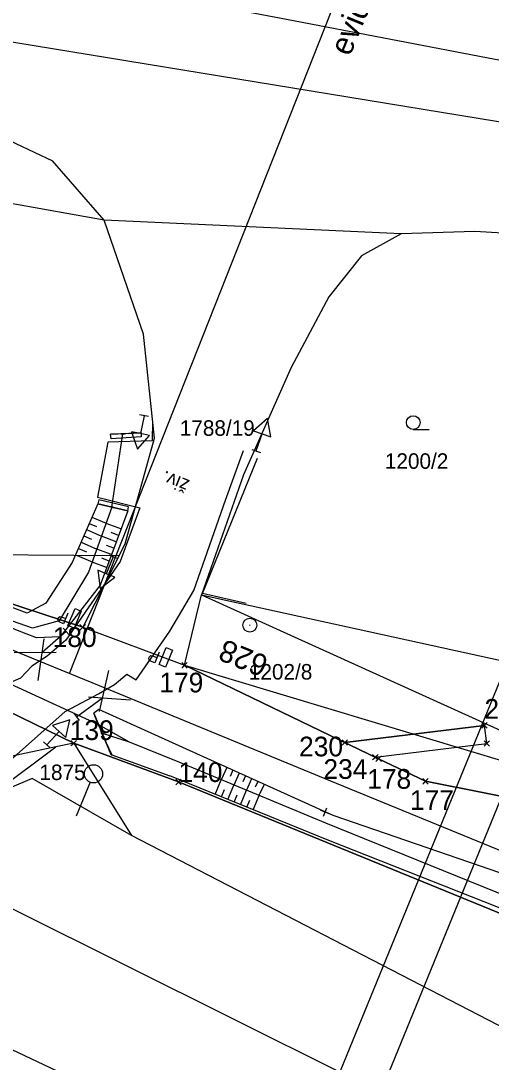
# Model space of a CAD drawing. Extents: x -779302 to -774398, y -1144902 to -1142831.
# Drawn here: x -776976.6 to -776925.1, y -1143911.3 to -1143797.2 of the extents above; entities that cross this region are included whole.
import ezdxf

# ---------------------------------------------------------------- set-up
doc = ezdxf.new("R2010")
doc.units = 0
for name, color, linetype in [('Dočasný zábor - do 1 roku - ZPF', 7, 'Continuous'), ('Hranice parcel', 7, 'Continuous'), ('legenda I_5_2 - Vrstva 53', 7, 'Continuous'), ('Parcelní čísla', 7, 'Continuous'), ('SŽDC', 7, 'Continuous'), ('VBř', 7, 'Continuous'), ('Vnitřní kresba', 7, 'Continuous'), ('Vrstva 1', 7, 'Continuous'), ('zjednodus_g_situ-seda - Vrstva 1', 7, 'Continuous'), ('zjednodus_g_situ-seda - Vrstva 17', 7, 'Continuous'), ('zjednodus_g_situ-seda - Vrstva 19', 7, 'Continuous'), ('zjednodus_g_situ-seda - Vrstva 33', 7, 'Continuous'), ('zjednodus_g_situ-seda - Vrstva 36', 7, 'Continuous'), ('zjednodus_g_situ-seda - Vrstva 4', 7, 'Continuous'), ('zjednodus_g_situ-seda - Vrstva 48', 7, 'Continuous'), ('zjednodus_g_situ-seda - Vrstva 49', 7, 'Continuous'), ('zjednodus_g_situ-seda - Vrstva 51', 7, 'Continuous'), ('zjednodus_g_situ-seda - Vrstva 63', 7, 'Continuous'), ('zjednodus_g_situ-seda - Vrstva 7', 7, 'Continuous'), ('Značky kultur', 7, 'Continuous')]:
    doc.layers.add(name, color=color, linetype=linetype)

msp = doc.modelspace()

# ---------------------------------------------------------------- linework, layer by layer
at = {"layer": 'Dočasný zábor - do 1 roku - ZPF'}
for p, q in [((-776941.1, -1143876.29), (-776925.79, -1143874.41)), ((-776925.79, -1143874.41), (-776941.1, -1143876.29)), ((-776925.54, -1143876.39), (-776925.79, -1143874.41)), ((-776941.1, -1143876.29), (-776937.76, -1143877.9)), ((-776937.76, -1143877.9), (-776925.54, -1143876.39)), ((-776937.76, -1143877.9), (-776937.76, -1143877.9))]:
    msp.add_line(p, q, dxfattribs=at)
msp.add_lwpolyline([(-776937.76, -1143877.9), (-776925.54, -1143876.39), (-776925.79, -1143874.41)], dxfattribs=at)
at = {"layer": 'Hranice parcel'}
for p, q in [((-776934.92, -1143820.52), (-776967.5, -1143819.04)), ((-776965.83, -1143855.79), (-776969.85, -1143863.66)), ((-776958.69, -1143867.83), (-776956.82, -1143860.1)), ((-776956.82, -1143860.1), (-776921.24, -1143867.89)), ((-776969.85, -1143863.66), (-776958.69, -1143867.83)), ((-776970.83, -1143876.37), (-776972.79, -1143876.78)), ((-776970.83, -1143876.37), (-776964.5, -1143886.48)), ((-776980.14, -1143882.23), (-776972.79, -1143876.78))]:
    msp.add_line(p, q, dxfattribs=at)
for points in [[(-776969.85, -1143863.66), (-776987.47, -1143857.88), (-777014.89, -1143846.57), (-777042.6, -1143836.95), (-777069.03, -1143828.43), (-777082.24, -1143824.08), (-777130.76, -1143810.13), (-777274.26, -1143769.36), (-777322.71, -1143754.8), (-777354.97, -1143745.11)], [(-777032.87, -1143780.76), (-777005.26, -1143786.02), (-776947.51, -1143797.01), (-776924.63, -1143801.37), (-776885.75, -1143807.75)], [(-776967.5, -1143819.04), (-777009.69, -1143811.52), (-777037.53, -1143806.56)], [(-776965.83, -1143855.79), (-776965.18, -1143854.52), (-776961.99, -1143842.94), (-776963.17, -1143831.52), (-776967.5, -1143819.04)], [(-776934.92, -1143820.52), (-776939.26, -1143822.95), (-776942.87, -1143827.42), (-776947, -1143835.19), (-776952.22, -1143846.94), (-776956.82, -1143860.1)], [(-776913.94, -1143821.03), (-776926.85, -1143820.27), (-776934.92, -1143820.52)], [(-777042.47, -1143834.85), (-777015.21, -1143843.76), (-776985.79, -1143855.66), (-776965.83, -1143855.79)], [(-776956.82, -1143860.1), (-776911.51, -1143880.63), (-776902.75, -1143884.6)], [(-777002.25, -1143861.05), (-776982.48, -1143870.69), (-776970.83, -1143876.37)], [(-776911.85, -1143884.6), (-776932.26, -1143880.54), (-776937.4, -1143878.07), (-776958.69, -1143867.83)], [(-776970.83, -1143876.37), (-776959.34, -1143880.62), (-776893.47, -1143907.54), (-776747.29, -1143966.09)], [(-776972.79, -1143876.78), (-776992.99, -1143881.07), (-776998.39, -1143882.22)], [(-776964.5, -1143886.48), (-776975.37, -1143880.22), (-776980.14, -1143882.23)], [(-776767.95, -1143981.96), (-776771.13, -1143981.54), (-776923.23, -1143907.82), (-776964.5, -1143886.48)], [(-776817.86, -1143983.94), (-776814.26, -1143974.07), (-776869.06, -1143948.13), (-776905.56, -1143930.42), (-776989.05, -1143888.84)], [(-776819.3, -1143987.88), (-776871.91, -1143959.94), (-776915.87, -1143938.7), (-776942.03, -1143926.84), (-776978.29, -1143909.65), (-777001.23, -1143897.87)]]:
    msp.add_lwpolyline(points, dxfattribs=at)
at = {"layer": 'legenda I_5_2 - Vrstva 53'}
for points in [[(-777442.54, -1143720.48), (-777400.53, -1143733.41), (-777370.73, -1143741.3), (-777366.62, -1143741.88), (-777364.22, -1143742.54), (-777360.64, -1143743.54), (-777354.97, -1143745.11), (-777322.71, -1143754.8), (-777274.26, -1143769.36), (-777130.76, -1143810.13), (-777082.24, -1143824.08), (-777069.03, -1143828.43), (-777042.6, -1143836.95), (-777014.89, -1143846.57), (-776987.47, -1143857.88), (-776969.85, -1143863.66), (-776958.69, -1143867.83), (-776937.4, -1143878.07), (-776932.26, -1143880.54), (-776911.85, -1143884.6)], [(-776893.47, -1143907.54), (-776959.34, -1143880.62), (-776970.83, -1143876.37), (-776982.48, -1143870.69)]]:
    msp.add_lwpolyline(points, dxfattribs=at)
at = {"layer": 'SŽDC'}
for p, q in [((-776969.65, -1143863.86), (-776970.15, -1143863.36)), ((-776969.65, -1143863.46), (-776970.15, -1143863.96)), ((-776970.05, -1143863.86), (-776969.55, -1143863.36)), ((-776970.05, -1143863.46), (-776969.55, -1143863.96)), ((-776969.85, -1143863.66), (-776969.85, -1143863.66)), ((-776958.49, -1143868.03), (-776958.99, -1143867.53)), ((-776958.89, -1143868.03), (-776958.39, -1143867.53)), ((-776958.49, -1143867.63), (-776958.99, -1143868.13)), ((-776958.89, -1143867.63), (-776958.39, -1143868.13)), ((-776958.69, -1143867.83), (-776958.69, -1143867.83)), ((-776970.63, -1143876.57), (-776971.13, -1143876.07)), ((-776970.63, -1143876.17), (-776971.13, -1143876.67)), ((-776971.03, -1143876.57), (-776970.53, -1143876.07)), ((-776971.03, -1143876.17), (-776970.53, -1143876.67)), ((-776970.83, -1143876.37), (-776970.83, -1143876.37)), ((-776937.2, -1143878.27), (-776937.7, -1143877.77)), ((-776937.2, -1143877.87), (-776937.7, -1143878.37)), ((-776937.6, -1143878.27), (-776937.1, -1143877.77)), ((-776937.6, -1143877.87), (-776937.1, -1143878.37)), ((-776937.4, -1143878.07), (-776937.4, -1143878.07)), ((-776959.14, -1143880.82), (-776959.64, -1143880.32)), ((-776959.14, -1143880.42), (-776959.64, -1143880.92)), ((-776959.54, -1143880.82), (-776959.04, -1143880.32)), ((-776959.54, -1143880.42), (-776959.04, -1143880.92)), ((-776959.34, -1143880.62), (-776959.34, -1143880.62)), ((-776932.06, -1143880.74), (-776932.56, -1143880.24)), ((-776932.06, -1143880.34), (-776932.56, -1143880.84)), ((-776932.46, -1143880.74), (-776931.96, -1143880.24)), ((-776932.46, -1143880.34), (-776931.96, -1143880.84)), ((-776932.26, -1143880.54), (-776932.26, -1143880.54))]:
    msp.add_line(p, q, dxfattribs=at)
for points in [[(-777442.54, -1143720.48), (-777400.53, -1143733.41), (-777370.73, -1143741.3), (-777366.62, -1143741.88), (-777364.22, -1143742.54), (-777360.64, -1143743.54), (-777354.97, -1143745.11), (-777322.71, -1143754.8), (-777274.26, -1143769.36), (-777130.76, -1143810.13), (-777082.24, -1143824.08), (-777069.03, -1143828.43), (-777042.6, -1143836.95), (-777014.89, -1143846.57), (-776987.47, -1143857.88), (-776969.85, -1143863.66), (-776958.69, -1143867.83), (-776937.4, -1143878.07), (-776932.26, -1143880.54), (-776911.85, -1143884.6)], [(-776098.59, -1144230.98), (-776104.51, -1144228.21), (-776116.08, -1144223.44), (-776126.28, -1144219.86), (-776203.96, -1144186.83), (-776252.27, -1144167.08), (-776325.22, -1144137.73), (-776342.13, -1144130.92), (-776434.38, -1144092.81), (-776527.2, -1144055.02), (-776604.66, -1144024.21), (-776606.85, -1144023.34), (-776609.89, -1144021.72), (-776627.91, -1144012.39), (-776712.36, -1143980.08), (-776747.29, -1143966.09), (-776893.47, -1143907.54), (-776959.34, -1143880.62), (-776970.83, -1143876.37), (-776982.48, -1143870.69)]]:
    msp.add_lwpolyline(points, dxfattribs=at)
at = {"layer": 'VBř'}
for p, q in [((-776941.1, -1143876.29), (-776925.79, -1143874.41)), ((-776925.79, -1143874.41), (-776941.1, -1143876.29)), ((-776925.59, -1143874.61), (-776926.09, -1143874.11)), ((-776925.59, -1143874.21), (-776926.09, -1143874.71)), ((-776925.99, -1143874.61), (-776925.49, -1143874.11)), ((-776925.99, -1143874.21), (-776925.49, -1143874.71)), ((-776925.54, -1143876.39), (-776925.79, -1143874.41)), ((-776925.79, -1143874.41), (-776925.79, -1143874.41)), ((-776940.9, -1143876.49), (-776941.4, -1143875.99)), ((-776940.9, -1143876.09), (-776941.4, -1143876.59)), ((-776941.3, -1143876.49), (-776940.8, -1143875.99)), ((-776941.3, -1143876.09), (-776940.8, -1143876.59)), ((-776941.1, -1143876.29), (-776937.76, -1143877.9)), ((-776941.1, -1143876.29), (-776941.1, -1143876.29)), ((-776937.76, -1143877.9), (-776925.54, -1143876.39)), ((-776925.34, -1143876.59), (-776925.84, -1143876.09)), ((-776925.34, -1143876.19), (-776925.84, -1143876.69)), ((-776925.74, -1143876.59), (-776925.24, -1143876.09)), ((-776925.74, -1143876.19), (-776925.24, -1143876.69)), ((-776925.54, -1143876.39), (-776925.54, -1143876.39)), ((-776937.56, -1143878.1), (-776938.06, -1143877.6)), ((-776937.56, -1143877.7), (-776938.06, -1143878.2)), ((-776937.96, -1143878.1), (-776937.46, -1143877.6)), ((-776937.96, -1143877.7), (-776937.46, -1143878.2))]:
    msp.add_line(p, q, dxfattribs=at)
msp.add_lwpolyline([(-776937.76, -1143877.9), (-776925.54, -1143876.39), (-776925.79, -1143874.41)], dxfattribs=at)
at = {"layer": 'Vnitřní kresba'}
for p, q in [((-776909.93, -1143810.58), (-776980.28, -1143799.08)), ((-776981.09, -1143808.78), (-776973.15, -1143812.54)), ((-776967.5, -1143819.04), (-776973.15, -1143812.54)), ((-776958.69, -1143867.83), (-776918.2, -1143879.97))]:
    msp.add_line(p, q, dxfattribs=at)
at = {"layer": 'Vrstva 1'}
for points in [[(-775713.68, -1144238.31), (-776879.99, -1143761.57), (-776992.36, -1144036.48), (-775826.05, -1144513.22)], [(-775828.78, -1144506.7), (-776985.84, -1144033.74), (-776877.25, -1143768.09), (-775720.2, -1144241.05)]]:
    msp.add_lwpolyline(points, close=True, dxfattribs=at)
at = {"layer": 'zjednodus_g_situ-seda - Vrstva 1'}
for points in [[(-776976.22, -1143866.7), (-776986.48, -1143862.49), (-776998.36, -1143857.65), (-777010.89, -1143852.7), (-777023.89, -1143847.77), (-777036.16, -1143843.3), (-777048.78, -1143838.91), (-777061.58, -1143834.66), (-777074.36, -1143830.6), (-777086.89, -1143826.8), (-777099.41, -1143823.17), (-777109.99, -1143820.13), (-777122.39, -1143816.56)], [(-776922.15, -1143888.92), (-776942.01, -1143880.78), (-776966.41, -1143870.74), (-776976.22, -1143866.7)]]:
    msp.add_lwpolyline(points, dxfattribs=at)
at = {"layer": 'zjednodus_g_situ-seda - Vrstva 17'}
msp.add_lwpolyline([(-776951.91, -1143861.07), (-776956.7, -1143859.96), (-776950.68, -1143845.13)], dxfattribs=at)
at = {"layer": 'zjednodus_g_situ-seda - Vrstva 19'}
for p, q in [((-776966.65, -1143850.49), (-776965.44, -1143842.46)), ((-776968.15, -1143874.33), (-776979.28, -1143869.22))]:
    msp.add_line(p, q, dxfattribs=at)
for points in [[(-776963.44, -1143842.35), (-776963.45, -1143842.79), (-776966.74, -1143843.01), (-776966.78, -1143842.48), (-776963.44, -1143842.35)], [(-776963.44, -1143842.35), (-776965.44, -1143842.46), (-776966.78, -1143842.48)], [(-776964.91, -1143850.88), (-776964.81, -1143850.44), (-776968.08, -1143849.68), (-776968.2, -1143850.12), (-776964.91, -1143850.88)], [(-776964.91, -1143850.88), (-776966.65, -1143850.49), (-776968.2, -1143850.12)], [(-776968.15, -1143874.33), (-776967.94, -1143874.75), (-776967.94, -1143874.76), (-776967.79, -1143875.29), (-776967.79, -1143875.28), (-776966.65, -1143877.66), (-776966.73, -1143877.64), (-776968.62, -1143873.09), (-776968.15, -1143874.33)]]:
    msp.add_lwpolyline(points, dxfattribs=at)
for centre, major_axis, ratio, start_param, end_param in [((-776965.47, -1143842.45), (-0.205, 0.006), 0.009306, 4.429767, 8.016952), ((-776965.47, -1143842.45), (-0.205, 0.006), 0.009306, 6.269557, 10.712953), ((-776966.62, -1143850.49), (-0.194, 0.054), 0.018197, 4.831006, 9.404932), ((-776966.62, -1143850.49), (-0.194, 0.054), 0.018197, 1.451935, 4.831006), ((-776968.19, -1143874.26), (0.135, -0.275), 0.012816, 1.330754, 4.921196), ((-776968.19, -1143874.26), (0.135, -0.275), 0.012816, 4.921196, 9.434774)]:
    msp.add_ellipse(centre, major_axis=major_axis, ratio=ratio, start_param=start_param, end_param=end_param, dxfattribs=at)
at = {"layer": 'zjednodus_g_situ-seda - Vrstva 33'}
for points in [[(-776970.77, -1143863.75), (-776971.46, -1143863.47), (-776970.69, -1143861.6), (-776970, -1143861.89)], [(-776960.78, -1143868.04), (-776961.46, -1143867.75), (-776960.7, -1143865.89), (-776960.01, -1143866.17)]]:
    msp.add_lwpolyline(points, close=True, dxfattribs=at)
for points in [[(-776971.47, -1143862.11), (-776971.94, -1143863.27), (-776972.43, -1143863.07), (-776972.55, -1143862.97), (-776972.58, -1143862.74), (-776972.54, -1143862.63), (-776972.35, -1143862.48), (-776972.19, -1143862.5), (-776971.71, -1143862.7)], [(-776961.47, -1143866.4), (-776961.95, -1143867.56), (-776962.43, -1143867.36), (-776962.56, -1143867.25), (-776962.58, -1143867.02), (-776962.54, -1143866.92), (-776962.36, -1143866.77), (-776962.19, -1143866.79), (-776961.71, -1143866.99)]]:
    msp.add_lwpolyline(points, dxfattribs=at)
at = {"layer": 'zjednodus_g_situ-seda - Vrstva 36'}
for p, q in [((-776968.66, -1143879.73), (-776968.66, -1143879.73)), ((-776969.04, -1143880.65), (-776970.56, -1143884.35))]:
    msp.add_line(p, q, dxfattribs=at)
msp.add_circle((-776968.66, -1143879.73), 1, dxfattribs=at)
at = {"layer": 'zjednodus_g_situ-seda - Vrstva 4'}
for p, q in [((-776971.31, -1143868.72), (-776937.22, -1143782.62)), ((-776971.65, -1143864.12), (-776974.29, -1143866.44)), ((-776971.32, -1143864.5), (-776971.98, -1143863.75)), ((-776974.73, -1143869.48), (-776974.07, -1143864.92)), ((-776972.76, -1143866.43), (-776977.37, -1143866.47)), ((-776966.41, -1143870.74), (-776976.22, -1143866.7)), ((-776967, -1143868.39), (-776968.03, -1143872.88)), ((-776970.52, -1143873.48), (-776967.69, -1143871.38)), ((-776969.22, -1143871.27), (-776964.62, -1143871.6)), ((-776970.81, -1143873.08), (-776970.22, -1143873.88))]:
    msp.add_line(p, q, dxfattribs=at)
at = {"layer": 'zjednodus_g_situ-seda - Vrstva 48'}
for p, q in [((-776968.83, -1143851.58), (-776967.28, -1143852.25)), ((-776969.13, -1143852.27), (-776968.33, -1143852.61)), ((-776965.65, -1143852.88), (-776967.29, -1143852.28)), ((-776969.73, -1143853.64), (-776968.89, -1143854.01)), ((-776969.43, -1143852.95), (-776967.79, -1143853.66)), ((-776966.17, -1143854.29), (-776967.8, -1143853.69)), ((-776965.91, -1143853.59), (-776966.73, -1143853.28)), ((-776970.32, -1143855.02), (-776969.44, -1143855.4)), ((-776970.02, -1143854.33), (-776968.3, -1143855.08)), ((-776966.43, -1143854.99), (-776967.24, -1143854.69)), ((-776970.62, -1143855.71), (-776968.81, -1143856.49)), ((-776966.69, -1143855.7), (-776968.31, -1143855.1)), ((-776966.95, -1143856.4), (-776967.76, -1143856.1)), ((-776967.22, -1143857.1), (-776968.82, -1143856.51)), ((-776954.06, -1143879.02), (-776954.68, -1143880.38)), ((-776953.38, -1143879.33), (-776953.68, -1143880)), ((-776952.69, -1143879.64), (-776953.29, -1143880.95)), ((-776952.01, -1143879.95), (-776952.3, -1143880.59)), ((-776955.32, -1143881.98), (-776954.67, -1143880.38)), ((-776953.93, -1143882.54), (-776953.29, -1143880.95)), ((-776951.33, -1143880.26), (-776951.9, -1143881.53)), ((-776950.65, -1143880.57), (-776950.93, -1143881.19)), ((-776949.96, -1143880.88), (-776950.52, -1143882.1)), ((-776954.62, -1143882.26), (-776954.3, -1143881.46)), ((-776953.23, -1143882.82), (-776952.91, -1143882.03)), ((-776952.54, -1143883.11), (-776951.9, -1143881.53)), ((-776951.15, -1143883.67), (-776950.51, -1143882.1)), ((-776951.84, -1143883.39), (-776951.53, -1143882.6))]:
    msp.add_line(p, q, dxfattribs=at)
at = {"layer": 'zjednodus_g_situ-seda - Vrstva 49'}
msp.add_line((-776964.91, -1143850.88), (-776968.2, -1143850.12), dxfattribs=at)
for points in [[(-776968.2, -1143850.12), (-776971, -1143856.57), (-776973.89, -1143861.01), (-776975.92, -1143862.12), (-776984.87, -1143858.78), (-776998.01, -1143853.19), (-777022.63, -1143844.17), (-777047.12, -1143835.12), (-777072.37, -1143826.98), (-777098.75, -1143819.43)], [(-776966.65, -1143850.49), (-776969.22, -1143857.63), (-776972.42, -1143862.97), (-776975.34, -1143863.74), (-776985.5, -1143860.23), (-776998.08, -1143854.94), (-777010.13, -1143850.49), (-777022.9, -1143845.63), (-777035.32, -1143841.2), (-777047.81, -1143836.56), (-777060.73, -1143832.38), (-777073.56, -1143828.16), (-777086.22, -1143824.49), (-777098.73, -1143820.87)], [(-776964.91, -1143850.88), (-776967.94, -1143859.05), (-776972.31, -1143864.71), (-776974.92, -1143864.81), (-776977.17, -1143863.94), (-776985.5, -1143860.23)], [(-776632.28, -1144010.5), (-776655.24, -1144000.62), (-776678.59, -1143991.16), (-776699.81, -1143982.69), (-776720.93, -1143974.16), (-776739.27, -1143966.19), (-776740.46, -1143965.68), (-776743.6, -1143964.4), (-776744.85, -1143963.84), (-776767.74, -1143955.02), (-776787.78, -1143946.98), (-776802.96, -1143940.45), (-776815.44, -1143935.53), (-776839.01, -1143925.84), (-776864.39, -1143915.25), (-776887.92, -1143905.39), (-776903.55, -1143899.04), (-776922.93, -1143890.99), (-776942.4, -1143884.3), (-776968.09, -1143872.66), (-776968.62, -1143873.09), (-776966.73, -1143877.64), (-776966.65, -1143877.66), (-776960.31, -1143879.96)], [(-776964.72, -1143876.26), (-776968.15, -1143874.33), (-776968.62, -1143873.09)], [(-776745.22, -1143966.39), (-776768.57, -1143956.81), (-776788.05, -1143948.79), (-776815.75, -1143937.29), (-776840.44, -1143927.18), (-776864.63, -1143917.51), (-776887.35, -1143908.08), (-776904.88, -1143900.89), (-776924.52, -1143892.68), (-776943.18, -1143885.14), (-776959.2, -1143878.5), (-776964.72, -1143876.26), (-776967.79, -1143875.28), (-776966.65, -1143877.66)], [(-776744.57, -1143967.58), (-776769.47, -1143958.42), (-776788.11, -1143949.89), (-776817.57, -1143938.46), (-776840.93, -1143928.5), (-776865.04, -1143918.88), (-776887.65, -1143909.3), (-776905.6, -1143902.46), (-776924.44, -1143894.29), (-776942.85, -1143887.03), (-776960.31, -1143879.96)]]:
    msp.add_lwpolyline(points, dxfattribs=at)
at = {"layer": 'zjednodus_g_situ-seda - Vrstva 51'}
for p, q in [((-776962.63, -1143840.57), (-776963.61, -1143840.37)), ((-776951.3, -1143844.16), (-776950.36, -1143844.5)), ((-776966.04, -1143856.13), (-776966.96, -1143855.75)), ((-776974.15, -1143876.22), (-776973.41, -1143876.89))]:
    msp.add_line(p, q, dxfattribs=at)
for points in [[(-776962.18, -1143841.03), (-776962.22, -1143843.23), (-776967.09, -1143843.36), (-776968.22, -1143849.4), (-776963.57, -1143850.58), (-776965.73, -1143856.44), (-776971.7, -1143865.07), (-776973.74, -1143866.81)], [(-776963.12, -1143840.47), (-776963.5, -1143842.43), (-776964.49, -1143842.24), (-776963.84, -1143844.15), (-776962.52, -1143842.62), (-776963.5, -1143842.43)], [(-776950.83, -1143844.33), (-776950.16, -1143842.44), (-776949.22, -1143842.78), (-776949.58, -1143840.79), (-776951.1, -1143842.11), (-776950.16, -1143842.44)], [(-776988.15, -1143887.44), (-776971.77, -1143872.89), (-776968.13, -1143870.95), (-776966.35, -1143869.93), (-776965.02, -1143868.81), (-776964, -1143869.42), (-776960.29, -1143864.08), (-776957.65, -1143859.63), (-776954.19, -1143849.74), (-776952.22, -1143844.27)], [(-776966.5, -1143855.94), (-776967.26, -1143857.79), (-776968.19, -1143857.41), (-776967.93, -1143859.41), (-776966.34, -1143858.17), (-776967.26, -1143857.79)], [(-776973.74, -1143866.81), (-776975.42, -1143867.93), (-776976.65, -1143869.24), (-776979.72, -1143870.56), (-776986.41, -1143871.78), (-776995.94, -1143871.02), (-777005.37, -1143868.87)], [(-776973.78, -1143876.56), (-776972.43, -1143875.08), (-776971.69, -1143875.75), (-776971.25, -1143873.79), (-776973.17, -1143874.41), (-776972.43, -1143875.08)]]:
    msp.add_lwpolyline(points, dxfattribs=at)
at = {"layer": 'zjednodus_g_situ-seda - Vrstva 63'}
msp.add_line((-776951.48, -1143863.45), (-776951.57, -1143863.41), dxfattribs=at)
msp.add_circle((-776951.52, -1143863.43), 0.756, dxfattribs=at)
at = {"layer": 'zjednodus_g_situ-seda - Vrstva 7'}
for p, q in [((-776943.46, -1143884.38), (-776943.08, -1143883.46)), ((-776942.81, -1143884.11), (-776943.73, -1143883.73))]:
    msp.add_line(p, q, dxfattribs=at)
at = {"layer": 'Značky kultur'}
msp.add_line((-776933.6, -1143841.97), (-776931.85, -1143841.97), dxfattribs=at)
msp.add_circle((-776933.6, -1143841.22), 0.75, dxfattribs=at)

# ---------------------------------------------------------------- texts
at = {"layer": 'Parcelní čísla'}
for s, p in [('1788/19', (-776959.2, -1143842.67)), ('1200/2', (-776936.71, -1143846.29)), ('1202/8', (-776951.62, -1143869.39)), ('1875', (-776974.59, -1143880.41))]:
    msp.add_text(s, height=1.7, dxfattribs=at).set_placement(p)
at = {"layer": 'SŽDC'}
for s, p in [('180', (-776973.14, -1143865.82)), ('179', (-776961.44, -1143870.8)), ('139', (-776971.26, -1143876.02)), ('140', (-776959.34, -1143880.62)), ('178', (-776938.65, -1143881.36)), ('177', (-776933.97, -1143883.68))]:
    msp.add_text(s, height=2.16, dxfattribs=at).set_placement(p)
at = {"layer": 'VBř'}
for s, p in [('231', (-776925.79, -1143873.68)), ('230', (-776946.12, -1143877.81)), ('234', (-776943.45, -1143880.28))]:
    msp.add_text(s, height=2.16, dxfattribs=at).set_placement(p)
at = {"layer": 'zjednodus_g_situ-seda - Vrstva 4'}
msp.add_text('evid. km 6,869', height=2.5, rotation=67.6334, dxfattribs=at).set_placement((-776940.55, -1143801.16))
at = {"layer": 'zjednodus_g_situ-seda - Vrstva 51'}
msp.add_text('živ.', height=1.5, rotation=158.1114, dxfattribs=at).set_placement((-776958.03, -1143847.57))
at = {"layer": 'zjednodus_g_situ-seda - Vrstva 63'}
msp.add_text('628', height=2.4, rotation=157.6214, dxfattribs=at).set_placement((-776949.3, -1143866.96))

doc.saveas('drawing.dxf')
